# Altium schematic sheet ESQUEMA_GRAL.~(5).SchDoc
size A3
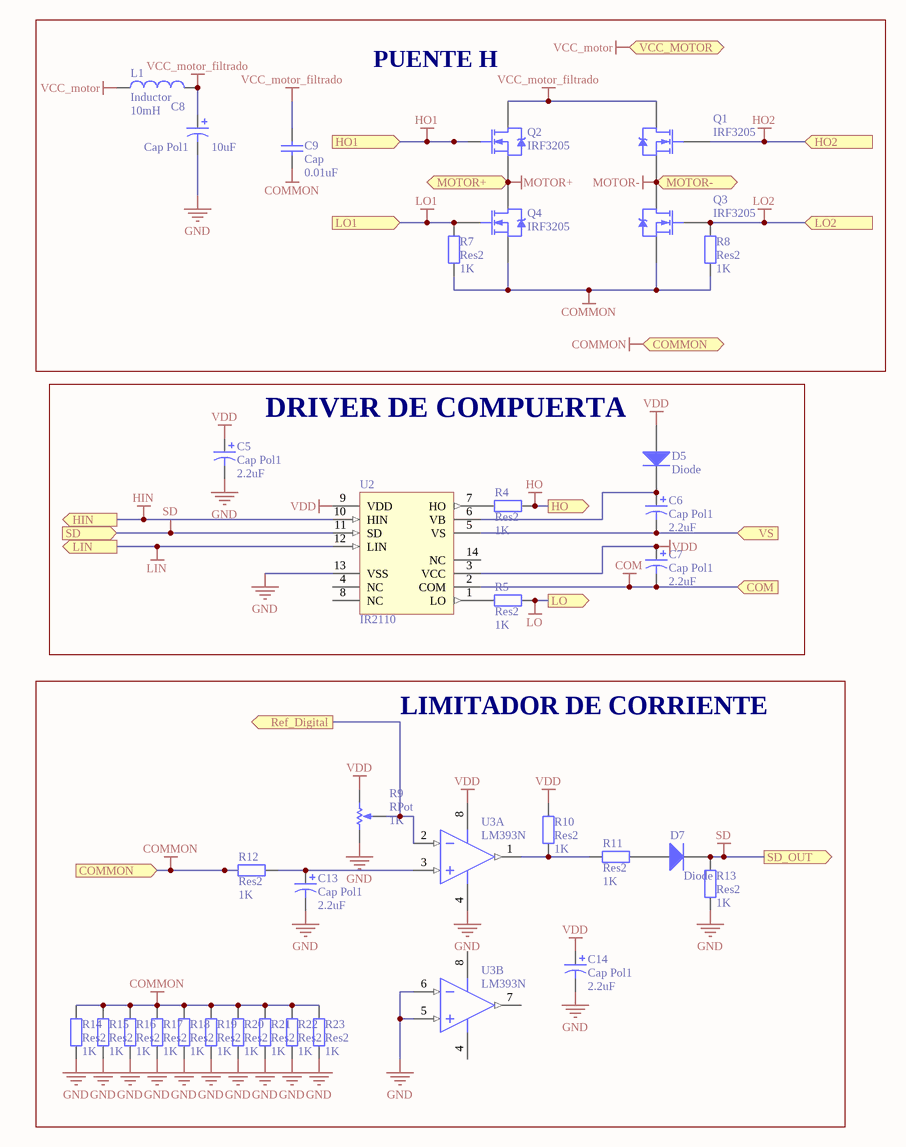
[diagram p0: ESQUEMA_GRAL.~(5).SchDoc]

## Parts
C5  Cap Pol1  value 2.2uF  [CAPPR2.5-6.3X5]
C6  Cap Pol1  value 2.2uF  [CAPPR2.5-6.3X5]
C7  Cap Pol1  value 2.2uF  [CAPPR2.5-6.3X5]
C8  Cap Pol1  value 10uF  [CAPPR5-13X16]
C9  Cap  value 0.01uF  [RAD-0.2]
C13  Cap Pol1  value 2.2uF  [CAPPR2.5-6.3X5]
C14  Cap Pol1  value 2.2uF  [CAPPR2.5-6.3X5]
D5  Diode  [DO-204AL]
D7  Diode  [DO-204AL]
L1  Inductor  value 10mH  [bobina_Choque]
Q1  IRF3205  [TO-220AB]
Q2  IRF3205  [TO-220AB]
Q3  IRF3205  [TO-220AB]
Q4  IRF3205  [TO-220AB]
R4  Res2  value 1K  [AXIAL-0.3]
R5  Res2  value 1K  [AXIAL-0.3]
R7  Res2  value 1K  [AXIAL-0.3]
R8  Res2  value 1K  [AXIAL-0.3]
R9  RPot  value 1K  [VR5]
R10  Res2  value 1K  [AXIAL-0.3]
R11  Res2  value 1K  [AXIAL-0.3]
R12  Res2  value 1K  [AXIAL-0.3]
R13  Res2  value 1K  [AXIAL-0.3]
R14  Res2  value 1K  [AXIAL-0.4]
R15  Res2  value 1K  [AXIAL-0.4]
R16  Res2  value 1K  [AXIAL-0.4]
R17  Res2  value 1K  [AXIAL-0.4]
R18  Res2  value 1K  [AXIAL-0.4]
R19  Res2  value 1K  [AXIAL-0.4]
R20  Res2  value 1K  [AXIAL-0.4]
R21  Res2  value 1K  [AXIAL-0.4]
R22  Res2  value 1K  [AXIAL-0.4]
R23  Res2  value 1K  [AXIAL-0.4]
U2  IR2110  [PDIP14]
U3  LM393N  [626-05]  (parts A,B of 2)

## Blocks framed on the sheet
PUENTE H: C8 C9 L1 Q1-Q4 R7 R8
DRIVER DE COMPUERTA: C5-C7 D5 R4 R5 U2
LIMITADOR DE CORRIENTE: C13 C14 D7 R9-R23 U3

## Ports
COM (in), COMMON (in), COMMON (out), HIN (out), HO1 (in), HO2 (in), HO (out), LIN (out), LO1 (in), LO2 (in), LO (out), MOTOR+ (bidir), MOTOR- (bidir), Ref_Digital (out), SD (in), SD_OUT (out), VCC_MOTOR (in), VS (in)

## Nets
COM: C7.2 U2.2(COM) ; port COM
COMMON: C9.1 Q3.3(S) Q4.3(S) R7.1 R8.1 R12.1 R14.2 R15.2 R16.2 R17.2 R18.2 R19.2 R20.2 R21.2 R22.2 R23.2 ; port COMMON
GND: C5.2 C8.2 C13.2 C14.2 R9.1(TOP) R13.1 R14.1 R15.1 R16.1 R17.1 R18.1 R19.1 R20.1 R21.1 R22.1 R23.1 U2.13(VSS) U3.4(GND) U3.5(IN+) U3.6(IN-)
HIN: U2.10(HIN) ; port HIN
HO: R4.2 ; port HO
HO1: Q2.1(G) ; port HO1
HO2: Q1.1(G) ; port HO2
LIN: U2.12(LIN) ; port LIN
LO: R5.2 ; port LO
LO1: Q4.1(G) R7.2 ; port LO1
LO2: Q3.1(G) R8.2 ; port LO2
MOTOR+: Q2.3(S) Q4.2(D) ; port MOTOR+
MOTOR-: Q1.3(S) Q3.2(D) ; port MOTOR-
SD: D7.2(K) R13.2 U2.11(SD) ; port SD, port SD_OUT
VCC_motor: L1.1 ; port VCC_MOTOR
VCC_motor_filtrado: C8.1 C9.2 L1.2 Q1.2(D) Q2.2(D)
VDD: C5.1 C7.1 C14.1 D5.1(A) R9.2(BOT) R10.2 U2.3(VCC) U2.9(VDD) U3.8(V+)
Ref_Digital: R9.3(TAP) U3.2(IN-) ; port Ref_Digital
VS: C6.2 U2.5(VS) ; port VS
NetC6_1: C6.1 D5.2(K) U2.6(VB)
NetC13_1: C13.1 R12.2 U3.3(IN+)
NetD7_1: D7.1(A) R11.2
NetR4_1: R4.1 U2.7(HO)
NetR5_1: R5.1 U2.1(LO)
NetR10_1: R10.1 R11.1 U3.1(OUT)

Not connected (* = marked no-connect by the designer): U2 4(NC) 8(NC) 14(NC); U3 7(OUT)

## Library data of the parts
C5-C8 C13 C14 = Cap Pol1: Polarized Capacitor (Radial)
C9 = Cap: Capacitor
D5 D7 = Diode: Default Diode
L1 = Inductor: Code_IEC: 1005
Q1-Q4 = IRF3205: HEXFET Power MOSFET; Note: Pin 2 is electrically connected to pin 4.
R4 R5 R7 R8 R10-R23 = Res2: Resistor
R9 = RPot: Potentiometer; Sim Note: Enter the Resistance value and the set point into parameter fields.; Set Position: 0.5
U2 = IR2110: High and Low Side Driver; Note: Pins 4, 8 and 14 are not connected
U3 = LM393N: Dual Comparator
